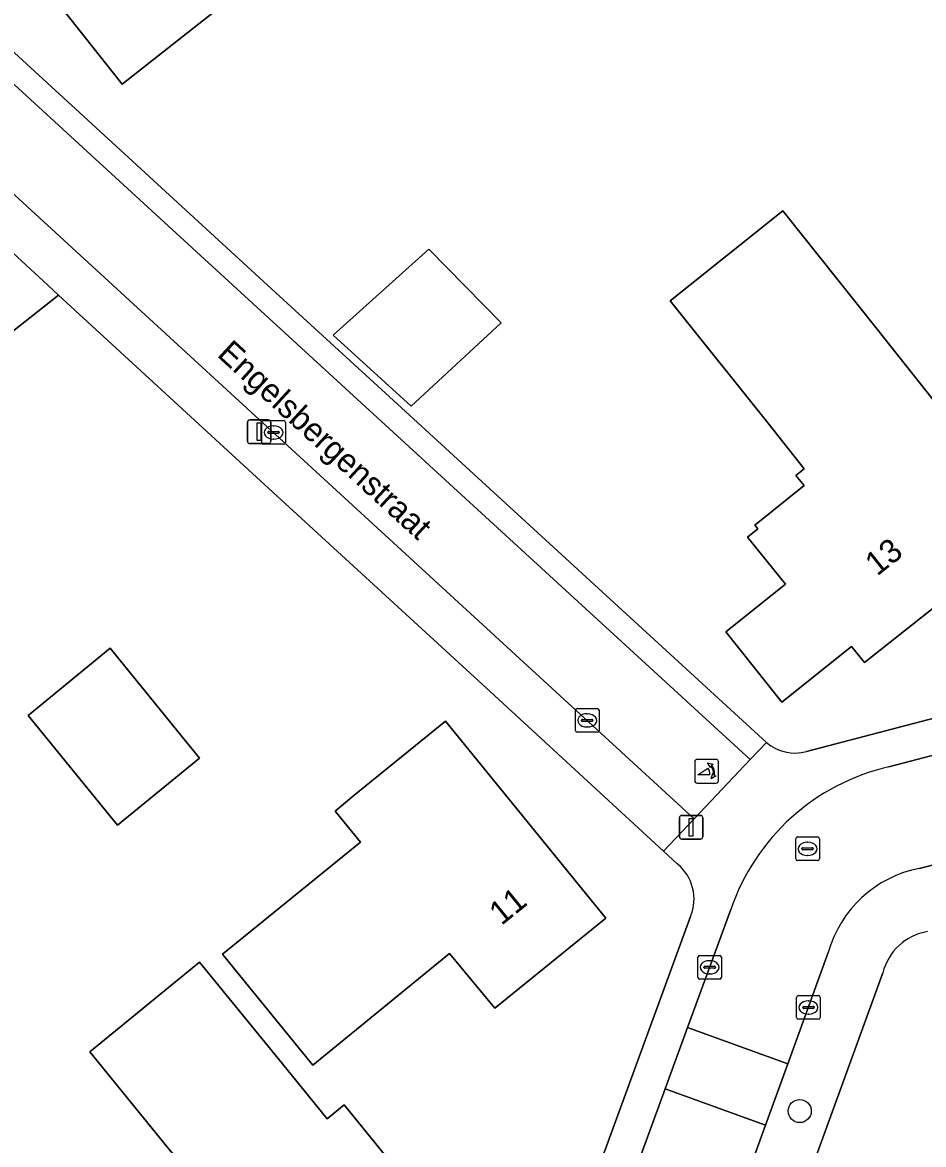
# Model space of a CAD drawing. Extents: x 159499 to 160349, y 382524 to 383273.
# Drawn here: x 159853.23 to 159891.37, y 382963.63 to 383011.11 of the extents above; entities that cross this region are included whole.
import ezdxf

# ---------------------------------------------------------------- set-up
doc = ezdxf.new("R2010")
doc.units = 0
for name, color, linetype in [('IMGEO_Boom', 7, 'Continuous'), ('IMGEO_Erf', 7, 'Continuous'), ('IMGEO_Kolk', 7, 'Continuous'), ('IMGEO_Lichtmast', 7, 'Continuous'), ('IMGEO_Muur', 7, 'Continuous'), ('IMGEO_Openbare_ruimte_label', 7, 'Continuous'), ('IMGEO_Pand', 7, 'Continuous'), ('IMGEO_Pand_nummerreeks', 7, 'Continuous'), ('IMGEO_Poller', 7, 'Continuous'), ('IMGEO_Rijbaan_lokaal_open', 7, 'Continuous'), ('IMGEO_Rioolput', 7, 'Continuous'), ('IMGEO_Voetpad_open', 7, 'Continuous')]:
    doc.layers.add(name, color=color, linetype=linetype)

msp = doc.modelspace()

# ---------------------------------------------------------------- linework, layer by layer
at = {"layer": 'IMGEO_Boom'}
msp.add_circle((159886.127, 382965.048), 0.489, dxfattribs=at)
at = {"layer": 'IMGEO_Erf'}
for points in [[(159980.466, 383082.767), (159973.363, 383091.624), (159970.403, 383089.263), (159966.602, 383094.029), (159959.746, 383088.563), (159957.137, 383091.836), (159954.02, 383095.745), (159961.123, 383101.385), (159963.162, 383098.828), (159964.427, 383097.24), (159967.154, 383099.413), (159965.906, 383101.017), (159961.847, 383106.236), (159961.699, 383106.426), (159884.908, 383045.395), (159855.273, 383021.828), (159846.991, 383015.242), (159863.606, 383000), (159868.935, 382995.116), (159884.721, 382980.647)], [(159868.941, 383015.881), (159867.337, 383014.614), (159866.519, 383015.65), (159857.453, 383008.492), (159853.668, 383013.286), (159854.183, 383013.698), (159853.436, 383014.669), (159861.261, 383020.851), (159862.033, 383019.883), (159862.828, 383020.516), (159862.056, 383021.485), (159864.251, 383023.221), (159866.435, 383024.948), (159867.181, 383023.997), (159867.959, 383024.609), (159867.212, 383025.559), (159874.715, 383031.505), (159875.483, 383030.545), (159876.016, 383030.932), (159879.114, 383027.008), (159883.899, 383020.949)], [(159880.946, 382975.51), (159880.365, 382976.048), (159872.852, 382982.952), (159864.016, 382991.071), (159854.762, 382999.575), (159851.919, 382997.338)], [(159886.41, 382980.261), (159915.857, 382987.966), (159920.985, 382989.308)], [(159873.068, 382950.247), (159874.989, 382955.474), (159881.51, 382973.281)], [(159889.642, 382970.897), (159882.889, 382952.318), (159881.976, 382949.835)]]:
    msp.add_lwpolyline(points, dxfattribs=at)
for points in [[(159894.942, 382991.159), (159893.091, 382989.678), (159894.215, 382988.264), (159888.873, 382984.022), (159888.321, 382984.712), (159885.369, 382982.351), (159882.993, 382985.322), (159885.518, 382987.338), (159883.921, 382989.337), (159884.351, 382989.68), (159884.221, 382989.845), (159886.312, 382991.518), (159885.968, 382991.947), (159886.32, 382992.228), (159884.772, 382994.165), (159880.641, 382999.333), (159885.405, 383003.14), (159889.353, 382998.199), (159891.833, 382995.075)], [(159869.677, 382994.881), (159866.376, 382997.884), (159870.422, 383001.52), (159873.492, 382998.394)], [(159853.465, 382981.792), (159856.946, 382984.629), (159860.722, 382979.98), (159857.249, 382977.149)], [(159867.256, 382978.394), (159871.132, 382981.551), (159877.915, 382973.204), (159873.216, 382969.407), (159871.299, 382971.712), (159865.524, 382966.993), (159862.365, 382970.869), (159861.703, 382971.682), (159867.531, 382976.428), (159866.458, 382977.744)], [(159858.277, 382953.914), (159856.128, 382956.551), (159861.485, 382960.917), (159859.401, 382963.476), (159856.076, 382967.554), (159860.728, 382971.345), (159864.053, 382967.267), (159866.126, 382964.724), (159866.841, 382965.306), (159871.055, 382960.136), (159867.947, 382957.602), (159867.72, 382957.882), (159866.511, 382956.896), (159869.152, 382953.656), (159864.157, 382949.557), (159862.804, 382951.165), (159861.436, 382950.038)]]:
    msp.add_lwpolyline(points, close=True, dxfattribs=at)
for centre, radius, start, end in [((159885.929, 382982.046), 1.849, 229.184, 285.0697), ((159879.714, 382974.012), 1.939, 337.8416, 50.5572), ((159891.929, 382970.316), 2.36, 99.5138, 165.7392)]:
    msp.add_arc(centre, radius, start, end, dxfattribs=at)
at = {"layer": 'IMGEO_Kolk'}
for p, q in [((159863.358, 382993.336), (159863.358, 382994.188)), ((159863.433, 382994.262), (159864.285, 382994.262)), ((159863.846, 382994.042), (159863.871, 382994.042)), ((159864.359, 382994.188), (159864.359, 382993.336)), ((159863.617, 382993.756), (159863.617, 382993.768)), ((159864.055, 382993.719), (159863.657, 382993.719)), ((159863.66, 382993.805), (159864.058, 382993.805)), ((159863.869, 382993.482), (159863.844, 382993.482)), ((159864.101, 382993.768), (159864.101, 382993.756)), ((159864.285, 382993.262), (159863.433, 382993.262)), ((159876.631, 382981.153), (159876.631, 382982.005)), ((159876.706, 382982.079), (159877.558, 382982.079)), ((159877.632, 382982.005), (159877.632, 382981.153)), ((159876.89, 382981.573), (159876.89, 382981.585)), ((159877.328, 382981.536), (159876.93, 382981.536)), ((159876.933, 382981.622), (159877.331, 382981.622)), ((159877.119, 382981.859), (159877.144, 382981.859)), ((159877.374, 382981.585), (159877.374, 382981.573)), ((159877.558, 382981.079), (159876.706, 382981.079)), ((159877.142, 382981.299), (159877.117, 382981.299)), ((159881.814, 382970.705), (159881.814, 382971.557)), ((159881.889, 382971.631), (159882.741, 382971.631)), ((159882.815, 382971.557), (159882.815, 382970.705)), ((159882.073, 382971.125), (159882.073, 382971.137)), ((159882.511, 382971.088), (159882.113, 382971.088)), ((159882.116, 382971.174), (159882.514, 382971.174)), ((159882.302, 382971.411), (159882.327, 382971.411)), ((159882.557, 382971.137), (159882.557, 382971.125)), ((159882.741, 382970.631), (159881.889, 382970.631)), ((159882.325, 382970.851), (159882.3, 382970.851)), ((159885.995, 382969.006), (159885.995, 382969.858)), ((159886.07, 382969.932), (159886.922, 382969.932)), ((159886.483, 382969.712), (159886.508, 382969.712)), ((159886.996, 382969.858), (159886.996, 382969.006)), ((159886.254, 382969.426), (159886.254, 382969.438)), ((159886.692, 382969.389), (159886.294, 382969.389)), ((159886.297, 382969.475), (159886.695, 382969.475)), ((159886.738, 382969.438), (159886.738, 382969.426)), ((159886.922, 382968.932), (159886.07, 382968.932)), ((159886.506, 382969.152), (159886.481, 382969.152))]:
    msp.add_line(p, q, dxfattribs=at)
for points in [[(159863.358, 382993.336), (159863.358, 382994.188)], [(159863.433, 382994.262), (159864.285, 382994.262)], [(159864.359, 382994.188), (159864.359, 382993.336)], [(159864.285, 382993.262), (159863.433, 382993.262)], [(159876.631, 382981.153), (159876.631, 382982.005)], [(159876.706, 382982.079), (159877.558, 382982.079)], [(159877.632, 382982.005), (159877.632, 382981.153)], [(159877.558, 382981.079), (159876.706, 382981.079)], [(159881.814, 382970.705), (159881.814, 382971.557)], [(159881.889, 382971.631), (159882.741, 382971.631)], [(159882.815, 382971.557), (159882.815, 382970.705)], [(159882.741, 382970.631), (159881.889, 382970.631)], [(159885.995, 382969.006), (159885.995, 382969.858)], [(159886.07, 382969.932), (159886.922, 382969.932)], [(159886.996, 382969.858), (159886.996, 382969.006)], [(159886.922, 382968.932), (159886.07, 382968.932)]]:
    msp.add_lwpolyline(points, dxfattribs=at)
for centre, radius, start, end in [((159863.435, 382994.186), 0.0765, 91.552, 178.448), ((159863.435, 382994.186), 0.0765, 91.552, 178.448), ((159864.283, 382994.186), 0.0765, 1.552, 88.448), ((159864.283, 382994.186), 0.0765, 1.552, 88.448), ((159863.657, 382993.765), 0.0403, 85.8775, 175.7526), ((159863.654, 382993.755), 0.0366, 178.938, 274.7102), ((159864.058, 382993.762), 0.043, 264.8664, 352.4533), ((159864.062, 382993.767), 0.0386, 1.7309, 96.639), ((159863.435, 382993.338), 0.0765, 181.552, 268.448), ((159863.435, 382993.338), 0.0765, 181.552, 268.448), ((159864.283, 382993.338), 0.0765, 271.552, 358.448), ((159864.283, 382993.338), 0.0765, 271.552, 358.448), ((159876.708, 382982.003), 0.0765, 91.552, 178.448), ((159876.708, 382982.003), 0.0765, 91.552, 178.448), ((159877.556, 382982.003), 0.0765, 1.552, 88.448), ((159877.556, 382982.003), 0.0765, 1.552, 88.448), ((159876.93, 382981.582), 0.0403, 85.8775, 175.7526), ((159876.927, 382981.572), 0.0366, 178.938, 274.7102), ((159877.331, 382981.579), 0.043, 264.8664, 352.4533), ((159877.335, 382981.584), 0.0386, 1.7309, 96.639), ((159876.708, 382981.155), 0.0765, 181.552, 268.448), ((159876.708, 382981.155), 0.0765, 181.552, 268.448), ((159877.556, 382981.155), 0.0765, 271.552, 358.448), ((159877.556, 382981.155), 0.0765, 271.552, 358.448), ((159881.891, 382971.555), 0.0765, 91.552, 178.448), ((159881.891, 382971.555), 0.0765, 91.552, 178.448), ((159882.739, 382971.555), 0.0765, 1.552, 88.448), ((159882.739, 382971.555), 0.0765, 1.552, 88.448), ((159882.113, 382971.134), 0.0403, 85.8775, 175.7526), ((159882.11, 382971.124), 0.0366, 178.938, 274.7102), ((159882.514, 382971.131), 0.043, 264.8664, 352.4533), ((159882.518, 382971.136), 0.0386, 1.7309, 96.639), ((159881.891, 382970.707), 0.0765, 181.552, 268.448), ((159881.891, 382970.707), 0.0765, 181.552, 268.448), ((159882.739, 382970.707), 0.0765, 271.552, 358.448), ((159882.739, 382970.707), 0.0765, 271.552, 358.448), ((159886.072, 382969.856), 0.0765, 91.552, 178.448), ((159886.072, 382969.856), 0.0765, 91.552, 178.448), ((159886.92, 382969.856), 0.0765, 1.552, 88.448), ((159886.92, 382969.856), 0.0765, 1.552, 88.448), ((159886.294, 382969.435), 0.0403, 85.8775, 175.7526), ((159886.291, 382969.425), 0.0366, 178.938, 274.7102), ((159886.695, 382969.432), 0.043, 264.8664, 352.4533), ((159886.699, 382969.437), 0.0386, 1.7309, 96.639), ((159886.072, 382969.008), 0.0765, 181.552, 268.448), ((159886.072, 382969.008), 0.0765, 181.552, 268.448), ((159886.92, 382969.008), 0.0765, 271.552, 358.448), ((159886.92, 382969.008), 0.0765, 271.552, 358.448)]:
    msp.add_arc(centre, radius, start, end, dxfattribs=at)
for centre, major_axis, ratio, start_param, end_param in [((159863.845, 382993.762), (-0.387, 0.002), 0.722429, 4.712389, 7.853982), ((159863.87, 382993.762), (-0.39, 0.002), 0.717154, 1.570796, 4.712389), ((159877.118, 382981.579), (-0.387, 0.002), 0.722429, 4.712389, 7.853982), ((159877.143, 382981.579), (-0.39, 0.002), 0.717154, 1.570796, 4.712389), ((159882.301, 382971.131), (-0.387, 0.002), 0.722429, 4.712389, 7.853982), ((159882.326, 382971.131), (-0.39, 0.002), 0.717154, 1.570796, 4.712389), ((159886.482, 382969.432), (-0.387, 0.002), 0.722429, 4.712389, 7.853982), ((159886.507, 382969.432), (-0.39, 0.002), 0.717154, 1.570796, 4.712389)]:
    msp.add_ellipse(centre, major_axis=major_axis, ratio=ratio, start_param=start_param, end_param=end_param, dxfattribs=at)
at = {"layer": 'IMGEO_Lichtmast'}
for p, q in [((159862.749, 382993.393), (159862.749, 382994.193)), ((159862.749, 382994.193), (159862.749, 382993.393)), ((159862.849, 382994.293), (159863.639, 382994.293)), ((159863.639, 382994.293), (159862.849, 382994.293)), ((159863.739, 382994.193), (159863.739, 382993.393)), ((159863.739, 382993.393), (159863.739, 382994.193)), ((159863.639, 382993.293), (159862.849, 382993.293)), ((159862.849, 382993.293), (159863.639, 382993.293)), ((159881.031, 382976.656), (159881.031, 382977.456)), ((159881.031, 382977.456), (159881.031, 382976.656)), ((159881.131, 382977.556), (159881.921, 382977.556)), ((159881.921, 382977.556), (159881.131, 382977.556)), ((159882.021, 382977.456), (159882.021, 382976.656)), ((159882.021, 382976.656), (159882.021, 382977.456)), ((159881.921, 382976.556), (159881.131, 382976.556)), ((159881.131, 382976.556), (159881.921, 382976.556))]:
    msp.add_line(p, q, dxfattribs=at)
for points in [[(159863.169, 382994.168), (159863.319, 382994.168), (159863.319, 382993.418), (159863.169, 382993.418), (159863.169, 382994.168)], [(159881.451, 382977.431), (159881.601, 382977.431), (159881.601, 382976.681), (159881.451, 382976.681), (159881.451, 382977.431)]]:
    msp.add_lwpolyline(points, dxfattribs=at)
for centre, start, end in [((159862.849, 382994.193), 90, 180), ((159862.849, 382994.193), 90, 180), ((159863.639, 382994.193), 0, 90), ((159863.639, 382994.193), 360, 90), ((159862.849, 382993.393), 180, 270), ((159862.849, 382993.393), 180, 270), ((159863.639, 382993.393), 270, 0), ((159863.639, 382993.393), 270, 0), ((159881.131, 382977.456), 90, 180), ((159881.131, 382977.456), 90, 180), ((159881.921, 382977.456), 0, 90), ((159881.921, 382977.456), 360, 90), ((159881.131, 382976.656), 180, 270), ((159881.131, 382976.656), 180, 270), ((159881.921, 382976.656), 270, 0), ((159881.921, 382976.656), 270, 0)]:
    msp.add_arc(centre, 0.1, start, end, dxfattribs=at)
at = {"layer": 'IMGEO_Muur'}
for points in [[(159868.935, 382995.116), (159884.721, 382980.647)], [(159872.852, 382982.952), (159864.016, 382991.071)]]:
    msp.add_lwpolyline(points, dxfattribs=at)
at = {"layer": 'IMGEO_Pand'}
for points in [[(159869.511, 383016.59), (159864.251, 383023.221), (159862.056, 383021.485), (159862.828, 383020.516), (159862.033, 383019.883), (159861.261, 383020.851), (159853.436, 383014.669), (159854.183, 383013.698), (159853.668, 383013.286), (159857.453, 383008.492), (159866.519, 383015.65), (159867.337, 383014.614), (159868.941, 383015.881)], [(159851.919, 382997.338), (159854.762, 382999.575), (159854.3, 383000), (159848.163, 383005.646)]]:
    msp.add_lwpolyline(points, dxfattribs=at)
for points in [[(159894.942, 382991.159), (159891.833, 382995.075), (159889.353, 382998.199), (159885.405, 383003.14), (159880.641, 382999.333), (159884.772, 382994.165), (159886.32, 382992.228), (159885.968, 382991.947), (159886.312, 382991.518), (159884.221, 382989.845), (159884.351, 382989.68), (159883.921, 382989.337), (159885.518, 382987.338), (159882.993, 382985.322), (159885.369, 382982.351), (159888.321, 382984.712), (159888.873, 382984.022), (159894.215, 382988.264), (159893.091, 382989.678)], [(159870.422, 383001.52), (159866.376, 382997.884), (159869.677, 382994.881), (159873.492, 382998.394)], [(159857.249, 382977.149), (159860.722, 382979.98), (159856.946, 382984.629), (159853.465, 382981.792)], [(159867.256, 382978.394), (159866.458, 382977.744), (159867.531, 382976.428), (159861.703, 382971.682), (159862.365, 382970.869), (159865.524, 382966.993), (159871.299, 382971.712), (159873.216, 382969.407), (159877.915, 382973.204), (159871.132, 382981.551)], [(159866.126, 382964.724), (159864.053, 382967.267), (159860.728, 382971.345), (159856.076, 382967.554), (159859.401, 382963.476), (159861.485, 382960.917), (159856.128, 382956.551), (159858.277, 382953.914), (159861.436, 382950.038), (159862.804, 382951.165), (159864.157, 382949.557), (159869.152, 382953.656), (159866.511, 382956.896), (159867.72, 382957.882), (159867.947, 382957.602), (159871.055, 382960.136), (159866.841, 382965.306)]]:
    msp.add_lwpolyline(points, close=True, dxfattribs=at)
at = {"layer": 'IMGEO_Poller'}
for p, q in [((159881.687, 382979.831), (159881.687, 382979.024)), ((159881.687, 382979.831), (159881.687, 382979.024)), ((159882.589, 382979.926), (159881.781, 382979.926)), ((159882.589, 382979.926), (159881.781, 382979.926)), ((159882.683, 382979.024), (159882.683, 382979.831)), ((159882.683, 382979.024), (159882.683, 382979.831)), ((159881.781, 382978.929), (159882.589, 382978.929)), ((159881.781, 382978.929), (159882.589, 382978.929))]:
    msp.add_line(p, q, dxfattribs=at)
for points in [[(159882.366, 382979.655), (159882.354, 382979.582), (159882.229, 382979.787)], [(159882.229, 382979.787), (159882.46, 382979.721), (159882.389, 382979.689)], [(159882.322, 382979.282), (159881.809, 382979.282), (159882.239, 382979.557)], [(159882.382, 382979.11), (159882.448, 382979.341), (159882.478, 382979.273)], [(159882.514, 382979.246), (159882.586, 382979.235), (159882.382, 382979.11)]]:
    msp.add_lwpolyline(points, dxfattribs=at)
for centre, radius, start, end in [((159881.781, 382979.831), 0.0946, 90, 180), ((159881.781, 382979.831), 0.0946, 90, 180), ((159882.008, 382979.342), 0.476, 351.7527, 41.1691), ((159882.008, 382979.342), 0.516, 349.3569, 42.2912), ((159882.589, 382979.831), 0.0946, 0, 90), ((159882.589, 382979.831), 0.0946, 0, 90), ((159881.994, 382979.332), 0.332, 351.3247, 42.4854), ((159881.781, 382979.024), 0.0946, 180, 270), ((159881.781, 382979.024), 0.0946, 180, 270), ((159882.589, 382979.024), 0.0946, 270, 0), ((159882.589, 382979.024), 0.0946, 270, 0)]:
    msp.add_arc(centre, radius, start, end, dxfattribs=at)
at = {"layer": 'IMGEO_Rijbaan_lokaal_open'}
for points in [[(159884.031, 382979.919), (159862.135, 383000), (159846.179, 383014.633), (159840.782, 383021.442), (159838.065, 383019.297), (159843.553, 383012.398), (159857.061, 383000), (159881.664, 382977.419)], [(159884.682, 382964.447), (159885.624, 382967.041), (159881.383, 382968.583), (159880.433, 382965.991)]]:
    msp.add_lwpolyline(points, close=True, dxfattribs=at)
for points in [[(159920.985, 382989.308), (159915.857, 382987.966), (159886.41, 382980.261)], [(159889.904, 382979.618), (159916.332, 382986.539), (159919.044, 382987.249), (159920.492, 382987.628), (159921.709, 382987.969)], [(159891.196, 382975.318), (159898.927, 382977.333), (159909.612, 382980.119), (159917.762, 382982.244), (159920.184, 382982.875), (159919.044, 382987.249), (159916.332, 382986.539), (159889.904, 382979.618)], [(159928.804, 382985.122), (159922.855, 382983.571), (159920.184, 382982.875), (159917.762, 382982.244), (159909.612, 382980.119), (159910.074, 382978.363), (159899.395, 382975.593), (159898.927, 382977.333), (159891.196, 382975.318)], [(159884.721, 382980.647), (159884.031, 382979.919), (159881.664, 382977.419), (159880.365, 382976.048), (159880.946, 382975.51)], [(159874.404, 382949.452), (159876.322, 382954.768), (159880.433, 382965.991), (159881.383, 382968.583), (159883.211, 382973.573)], [(159883.211, 382973.573), (159881.383, 382968.583), (159885.624, 382967.041), (159887.336, 382971.754)], [(159881.51, 382973.281), (159874.989, 382955.474), (159873.068, 382950.247)], [(159887.336, 382971.754), (159885.624, 382967.041), (159884.682, 382964.447), (159879.911, 382951.31)], [(159881.976, 382949.835), (159882.889, 382952.318), (159889.642, 382970.897)], [(159879.911, 382951.31), (159884.682, 382964.447), (159880.433, 382965.991), (159876.322, 382954.768), (159874.404, 382949.452), (159879.627, 382940.809), (159879.787, 382940.656), (159881.307, 382939.023), (159908.873, 382910.281), (159927.427, 382890.935), (159928.789, 382892.248), (159932.489, 382895.814), (159929.428, 382899.056), (159936.535, 382905.918), (159935.493, 382907.023), (159932.4, 382910.308), (159927.32, 382905.439)]]:
    msp.add_lwpolyline(points, dxfattribs=at)
for centre, radius, start, end in [((159885.929, 382982.046), 1.849, 229.184, 285.0697), ((159891.988, 382970.583), 9.273, 102.989, 161.1866), ((159891.988, 382970.583), 9.273, 102.989, 161.1866), ((159879.714, 382974.012), 1.939, 337.8416, 50.5572), ((159892.138, 382970.425), 4.983, 100.8996, 164.534), ((159892.138, 382970.425), 4.983, 100.8996, 164.534), ((159891.929, 382970.316), 2.36, 99.5138, 165.7392)]:
    msp.add_arc(centre, radius, start, end, dxfattribs=at)
at = {"layer": 'IMGEO_Rioolput'}
for p, q in [((159885.958, 382975.72), (159885.958, 382976.572)), ((159886.033, 382976.646), (159886.885, 382976.646)), ((159886.446, 382976.426), (159886.471, 382976.426)), ((159886.959, 382976.572), (159886.959, 382975.72)), ((159886.217, 382976.14), (159886.217, 382976.152)), ((159886.655, 382976.103), (159886.257, 382976.103)), ((159886.26, 382976.189), (159886.658, 382976.189)), ((159886.469, 382975.866), (159886.444, 382975.866)), ((159886.701, 382976.152), (159886.701, 382976.14)), ((159886.885, 382975.646), (159886.033, 382975.646))]:
    msp.add_line(p, q, dxfattribs=at)
for points in [[(159885.958, 382975.72), (159885.958, 382976.572)], [(159886.033, 382976.646), (159886.885, 382976.646)], [(159886.959, 382976.572), (159886.959, 382975.72)], [(159886.885, 382975.646), (159886.033, 382975.646)]]:
    msp.add_lwpolyline(points, dxfattribs=at)
for centre, radius, start, end in [((159886.035, 382976.57), 0.0765, 91.552, 178.448), ((159886.035, 382976.57), 0.0765, 91.552, 178.448), ((159886.883, 382976.57), 0.0765, 1.552, 88.448), ((159886.883, 382976.57), 0.0765, 1.552, 88.448), ((159886.257, 382976.149), 0.0403, 85.8775, 175.7526), ((159886.254, 382976.139), 0.0366, 178.938, 274.7102), ((159886.658, 382976.146), 0.043, 264.8664, 352.4533), ((159886.662, 382976.151), 0.0386, 1.7309, 96.639), ((159886.035, 382975.722), 0.0765, 181.552, 268.448), ((159886.035, 382975.722), 0.0765, 181.552, 268.448), ((159886.883, 382975.722), 0.0765, 271.552, 358.448), ((159886.883, 382975.722), 0.0765, 271.552, 358.448)]:
    msp.add_arc(centre, radius, start, end, dxfattribs=at)
for centre, major_axis, ratio, start_param, end_param in [((159886.445, 382976.146), (-0.387, 0.002), 0.722429, 4.712389, 7.853982), ((159886.47, 382976.146), (-0.39, 0.002), 0.717154, 1.570796, 4.712389)]:
    msp.add_ellipse(centre, major_axis=major_axis, ratio=ratio, start_param=start_param, end_param=end_param, dxfattribs=at)
at = {"layer": 'IMGEO_Voetpad_open'}
for points in [[(159843.659, 383023.682), (159840.782, 383021.442), (159846.179, 383014.633), (159862.135, 383000), (159884.031, 382979.919), (159884.721, 382980.647), (159868.935, 382995.116), (159863.606, 383000), (159846.991, 383015.242), (159855.273, 383021.828)], [(159830.239, 383005.093), (159831.784, 383003.185), (159842.05, 383011.31), (159848.163, 383005.646), (159854.3, 383000), (159854.762, 382999.575), (159864.016, 382991.071), (159872.852, 382982.952), (159880.365, 382976.048), (159881.664, 382977.419), (159857.061, 383000), (159843.553, 383012.398), (159838.065, 383019.297)]]:
    msp.add_lwpolyline(points, dxfattribs=at)

# ---------------------------------------------------------------- texts
at = {"layer": 'IMGEO_Openbare_ruimte_label'}
msp.add_text('Engelsbergenstraat', height=1, rotation=317.472, dxfattribs=at).set_placement((159861.426, 382997.011))
at = {"layer": 'IMGEO_Pand_nummerreeks'}
for s, rotation, p in [('13', 38.4512, (159889.401, 382987.659)), ('11', 38.9397, (159873.499, 382972.875))]:
    msp.add_text(s, height=1, rotation=rotation, dxfattribs=at).set_placement(p)

doc.saveas('drawing.dxf')
